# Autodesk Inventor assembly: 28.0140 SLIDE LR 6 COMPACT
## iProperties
Created: 2012-04
Part Number: 28.0140 SLIDE LR 6 COMPACT
Document SubType Name: Assembly
Designer: Administrator
Author: Administrator
